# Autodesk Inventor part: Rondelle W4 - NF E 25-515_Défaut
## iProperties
Shininess: 64.0
Length Units: 11269
Angle Units: 11279
Time Units: 11290
Mass Units: 11283
Length Display Precision: 3
Angle Display Precision: 2
Compacted: True
Part Number: Rondelle W4 - NF E 25-515_Défaut
Document SubType Name: Modeling
Created: 2006-01
Material: Par défaut
Designer: riri
Density: 0.0
Volumn: 0.0
Area: 0.0
PropertySet Name: Model Information
Control State: 0
Master: False
Checked Out: False
Author: riri
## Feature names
1. Base1
